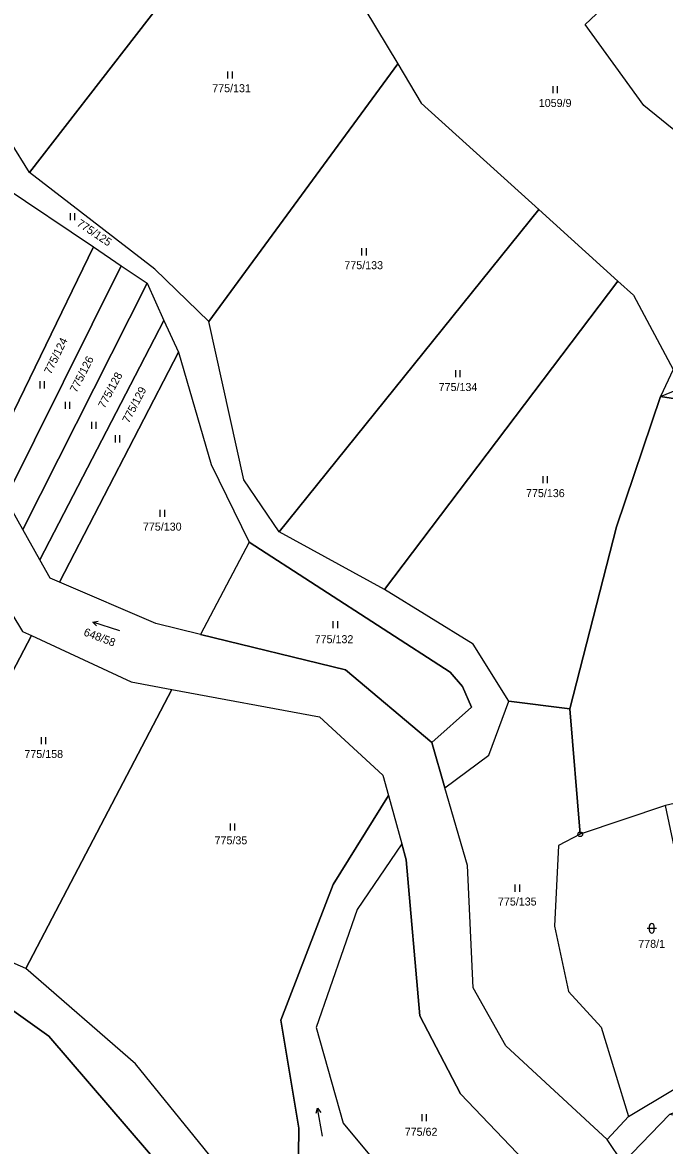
# Model space of a CAD drawing. Extents: x -654083 to -650132, y -1099819 to -1096699.
# Drawn here: x -653279.3 to -653142.9, y -1098231 to -1097992.4 of the extents above; entities that cross this region are included whole.
import ezdxf

# ---------------------------------------------------------------- set-up
doc = ezdxf.new("R2010")
doc.units = 0
for name, color, linetype in [('Geodetické body', 7, 'Continuous'), ('Obvody jako plochy', 7, 'Continuous'), ('Parcelní čísla', 7, 'Continuous'), ('Značky kultur', 7, 'Continuous')]:
    doc.layers.add(name, color=color, linetype=linetype)

msp = doc.modelspace()

# ---------------------------------------------------------------- linework, layer by layer
at = {"layer": 'Geodetické body'}
for radius in [0.5, 0.001]:
    msp.add_circle((-653160.81, -1098164.87), radius, dxfattribs=at)
at = {"layer": 'Obvody jako plochy'}
for points in [[(-653159.78, -1097992.82), (-653143.05, -1097977.01), (-653174.94, -1097944.83), (-653220.04, -1097975.33), (-653208.83, -1097985.73), (-653199.6, -1098001.2), (-653194.63, -1098009.53), (-653169.63, -1098032.13), (-653152.81, -1098047.34), (-653149.48, -1098050.35), (-653141.08, -1098066.12), (-653143.72, -1098071.82), (-653107.4, -1098056.94), (-653116.37, -1098047.99), (-653124.61, -1098033.31), (-653133.37, -1098021.26), (-653147.28, -1098010.02)], [(-653232.34, -1097965.52), (-653277.85, -1098024.22), (-653290.05, -1098004.68), (-653291.32, -1098003.86), (-653255.74, -1097953.38), (-653248.25, -1097960.84), (-653236.61, -1097962.12)], [(-653199.6, -1098001.2), (-653239.71, -1098055.94), (-653251.2, -1098044.79), (-653277.85, -1098024.22), (-653232.34, -1097965.52), (-653220.04, -1097975.33), (-653208.83, -1097985.73)], [(-653075.5, -1098032.29), (-653107.4, -1098056.94), (-653116.37, -1098047.99), (-653124.61, -1098033.31), (-653133.37, -1098021.26), (-653147.28, -1098010.02), (-653159.78, -1097992.82), (-653143.05, -1097977.01), (-653139.93, -1097974.11), (-653120.37, -1097998.7), (-653111.98, -1097991.16)], [(-653199.6, -1098001.2), (-653194.63, -1098009.53), (-653169.63, -1098032.13), (-653224.76, -1098100.64), (-653232.3, -1098089.58), (-653239.71, -1098055.94)], [(-653264.25, -1098040.07), (-653286.85, -1098086.54), (-653301, -1098061.42), (-653283.44, -1098027.14)], [(-653152.81, -1098047.34), (-653202.43, -1098112.89), (-653224.76, -1098100.64), (-653169.63, -1098032.13)], [(-653062.45, -1098049.88), (-653095.19, -1098080.64), (-653080.27, -1098096.44), (-653086.3, -1098093.39), (-653094.72, -1098096.79), (-653094.8, -1098106.24), (-653091.4, -1098111.38), (-653093.32, -1098113.17), (-653082.85, -1098128.85), (-653092.97, -1098135.64), (-653098.84, -1098139.62), (-653102.23, -1098135.55), (-653108.65, -1098140.04), (-653107.47, -1098141.62), (-653110.73, -1098144.07), (-653108.39, -1098146.98), (-653112.54, -1098150.18), (-653101.36, -1098101.34), (-653107.45, -1098091.76), (-653131.48, -1098073.76), (-653143.72, -1098071.82), (-653107.4, -1098056.94), (-653075.5, -1098032.29), (-653069, -1098038.01)], [(-653264.25, -1098040.07), (-653258.36, -1098044.1), (-653282.94, -1098093.51), (-653286.85, -1098086.54)], [(-653252.87, -1098047.8), (-653279.24, -1098100.09), (-653282.94, -1098093.51), (-653258.36, -1098044.1)], [(-653249.27, -1098055.67), (-653275.62, -1098106.54), (-653279.24, -1098100.09), (-653252.87, -1098047.8)], [(-653153.06, -1098099.55), (-653163, -1098138.19), (-653175.95, -1098136.58), (-653183.53, -1098124.46), (-653202.43, -1098112.89), (-653152.81, -1098047.34), (-653149.48, -1098050.35), (-653141.08, -1098066.12), (-653143.72, -1098071.82)], [(-653246.19, -1098062.4), (-653271.47, -1098111.27), (-653273.43, -1098110.43), (-653275.62, -1098106.54), (-653249.27, -1098055.67)], [(-653231.16, -1098102.79), (-653241.47, -1098122.39), (-653251.01, -1098120.05), (-653271.47, -1098111.27), (-653246.19, -1098062.4), (-653239.26, -1098086.27)], [(-653143.72, -1098071.82), (-653131.48, -1098073.76), (-653107.45, -1098091.76), (-653101.36, -1098101.34), (-653112.54, -1098150.18), (-653132.3, -1098156.38), (-653142.69, -1098158.75), (-653160.81, -1098164.87), (-653163, -1098138.19), (-653153.06, -1098099.55)], [(-653210.7, -1098129.94), (-653192.35, -1098145.37), (-653183.94, -1098137.86), (-653185.79, -1098133.47), (-653188.42, -1098130.41), (-653231.16, -1098102.79), (-653241.47, -1098122.39)], [(-653281.57, -1098118.02), (-653279.31, -1098121.79), (-653277.44, -1098122.65), (-653307.83, -1098180.61), (-653313.14, -1098178.29)], [(-653256.22, -1098132.47), (-653247.61, -1098134.08), (-653278.65, -1098193.38), (-653307.83, -1098180.61), (-653277.44, -1098122.65)], [(-653201.54, -1098156.66), (-653213.29, -1098175.51), (-653224.46, -1098204.35), (-653220.62, -1098227.34), (-653220.95, -1098256.03), (-653255.32, -1098213.68), (-653278.65, -1098193.38), (-653247.61, -1098134.08), (-653216.22, -1098139.94), (-653202.73, -1098152.28)], [(-653163.28, -1098198.26), (-653156.38, -1098205.89), (-653150.52, -1098224.84), (-653155.1, -1098229.74), (-653176.58, -1098209.82), (-653183.57, -1098197.47), (-653184.77, -1098171.52), (-653189.55, -1098155.03), (-653180.25, -1098148.05), (-653175.95, -1098136.58), (-653163, -1098138.19), (-653160.81, -1098164.87), (-653165.45, -1098167.24), (-653166.29, -1098184.39)], [(-653211.22, -1098226.27), (-653198.9, -1098241.01), (-653192.05, -1098259.39), (-653201.58, -1098268.37), (-653203.19, -1098270.41), (-653205.96, -1098270.01), (-653220.95, -1098256.03), (-653220.62, -1098227.34), (-653224.46, -1098204.35), (-653213.29, -1098175.51), (-653201.54, -1098156.66), (-653198.75, -1098166.88), (-653208.24, -1098180.85), (-653216.9, -1098205.95)], [(-653140.06, -1098171.16), (-653142.69, -1098158.75), (-653160.81, -1098164.87), (-653165.45, -1098167.24), (-653166.29, -1098184.39), (-653163.28, -1098198.26), (-653156.38, -1098205.89), (-653150.52, -1098224.84), (-653141.18, -1098219.21), (-653127.65, -1098213.56), (-653113.09, -1098212.74), (-653113.57, -1098209.43), (-653115.41, -1098203.29), (-653128.45, -1098206.67), (-653133.29, -1098186.91), (-653120.36, -1098183.92), (-653123.61, -1098174.68), (-653124.29, -1098173.63), (-653125.55, -1098167.69), (-653129.48, -1098168.54)], [(-653211.22, -1098226.27), (-653198.9, -1098241.01), (-653192.05, -1098259.39), (-653168.2, -1098238.96), (-653186.25, -1098220.02), (-653194.9, -1098203.46), (-653197.82, -1098170.31), (-653198.75, -1098166.88), (-653208.24, -1098180.85), (-653216.9, -1098205.95)], [(-653127.42, -1098218.94), (-653141.81, -1098224.4), (-653151.72, -1098234.65), (-653155.1, -1098229.74), (-653150.52, -1098224.84), (-653141.18, -1098219.21), (-653127.65, -1098213.56), (-653113.09, -1098212.74), (-653105.4, -1098235.64), (-653102.24, -1098235.17), (-653085.2, -1098247.42), (-653065.64, -1098241.83), (-653054.02, -1098216.68), (-653048.02, -1098219.45), (-653064.64, -1098245.21), (-653086.06, -1098253.64), (-653103.37, -1098243.32), (-653109.58, -1098237.03), (-653116.05, -1098224.73)], [(-653048.96, -1098245.31), (-653063.01, -1098264.63), (-653087.72, -1098268.11), (-653105.63, -1098249.24), (-653116.57, -1098235.54), (-653130.71, -1098226.18), (-653141.81, -1098224.4), (-653151.72, -1098234.65), (-653150.15, -1098236.92), (-653136.87, -1098239.39), (-653120.82, -1098247.61), (-653110.51, -1098257.89), (-653089.48, -1098275.9), (-653070.83, -1098275.94), (-653057.26, -1098272.93), (-653042.19, -1098261.25), (-653040.62, -1098245.28), (-653041.08, -1098237.12)]]:
    msp.add_lwpolyline(points, close=True, dxfattribs=at)
for points in [[(-653283.44, -1098027.14), (-653264.25, -1098040.07), (-653258.36, -1098044.1), (-653252.87, -1098047.8), (-653249.27, -1098055.67), (-653246.19, -1098062.4), (-653239.26, -1098086.27), (-653231.16, -1098102.79), (-653188.42, -1098130.41), (-653185.79, -1098133.47), (-653183.94, -1098137.86), (-653192.35, -1098145.37), (-653189.55, -1098155.03), (-653180.25, -1098148.05), (-653175.95, -1098136.58), (-653183.53, -1098124.46), (-653202.43, -1098112.89), (-653224.76, -1098100.64), (-653232.3, -1098089.58), (-653239.71, -1098055.94), (-653251.2, -1098044.79), (-653277.85, -1098024.22), (-653290.05, -1098004.68)], [(-653151.72, -1098234.65), (-653155.1, -1098229.74), (-653176.58, -1098209.82), (-653183.57, -1098197.47), (-653184.77, -1098171.52), (-653189.55, -1098155.03), (-653192.35, -1098145.37), (-653210.7, -1098129.94), (-653241.47, -1098122.39), (-653251.01, -1098120.05), (-653271.47, -1098111.27), (-653273.43, -1098110.43), (-653275.62, -1098106.54), (-653279.24, -1098100.09), (-653282.94, -1098093.51)], [(-653220.95, -1098256.03), (-653255.32, -1098213.68), (-653278.65, -1098193.38), (-653307.83, -1098180.61), (-653313.14, -1098178.29), (-653318.28, -1098177.23), (-653324.7, -1098175.91), (-653330.85, -1098174.66), (-653343.74, -1098171.99), (-653355.99, -1098171.56), (-653368.93, -1098171.02), (-653380.57, -1098166.58), (-653399.87, -1098159.66), (-653405.94, -1098157.48), (-653412.2, -1098155.23), (-653418.76, -1098152.53), (-653438.8, -1098143.39), (-653448.64, -1098138.64), (-653459.37, -1098133.66), (-653470.35, -1098127.79), (-653479.94, -1098122.66), (-653491.36, -1098116.55), (-653503.03, -1098110.31)], [(-653281.57, -1098118.02), (-653279.31, -1098121.79), (-653277.44, -1098122.65), (-653256.22, -1098132.47), (-653247.61, -1098134.08), (-653216.22, -1098139.94), (-653202.73, -1098152.28), (-653201.54, -1098156.66), (-653198.75, -1098166.88), (-653197.82, -1098170.31), (-653194.9, -1098203.46), (-653186.25, -1098220.02), (-653168.2, -1098238.96)], [(-653493.48, -1098120.72), (-653482.17, -1098127.04), (-653472.69, -1098132.34), (-653461.42, -1098138.22), (-653451, -1098142.87), (-653440.64, -1098147.5), (-653420.66, -1098156.42), (-653413.9, -1098158.8), (-653407.86, -1098160.93), (-653401.5, -1098163.17), (-653382.27, -1098169.95), (-653370.67, -1098173.73), (-653358.4, -1098174.67), (-653342.34, -1098175.9), (-653332.88, -1098178.02), (-653326.43, -1098179.47), (-653320.16, -1098180.87), (-653314.95, -1098182.04), (-653308.89, -1098183.4), (-653311.64, -1098188.12), (-653291.44, -1098195.15), (-653273.74, -1098207.76), (-653248.25, -1098237.42)], [(-653248.25, -1098237.42), (-653273.74, -1098207.76), (-653291.44, -1098195.15), (-653311.64, -1098188.12), (-653317.13, -1098186.57), (-653319.71, -1098185.85), (-653323.45, -1098187.25), (-653331.7, -1098190.34), (-653336.25, -1098192.05), (-653345, -1098208.95), (-653339.77, -1098228.47), (-653333.68, -1098254.4)]]:
    msp.add_lwpolyline(points, dxfattribs=at)
at = {"layer": 'Značky kultur'}
for p, q in [((-653235.75, -1098002.76), (-653235.75, -1098004.26)), ((-653234.72, -1098004.26), (-653234.72, -1098002.76)), ((-653166.64, -1098005.9), (-653166.64, -1098007.4)), ((-653165.61, -1098007.4), (-653165.61, -1098005.9)), ((-653269.21, -1098032.89), (-653269.21, -1098034.39)), ((-653268.19, -1098034.39), (-653268.19, -1098032.89)), ((-653207.28, -1098040.36), (-653207.28, -1098041.86)), ((-653206.26, -1098041.86), (-653206.26, -1098040.36)), ((-653187.32, -1098066.26), (-653187.32, -1098067.76)), ((-653186.3, -1098067.76), (-653186.3, -1098066.26)), ((-653275.67, -1098068.62), (-653275.67, -1098070.12)), ((-653274.65, -1098070.12), (-653274.65, -1098068.62)), ((-653270.29, -1098072.96), (-653270.29, -1098074.46)), ((-653269.27, -1098074.46), (-653269.27, -1098072.96)), ((-653264.67, -1098077.22), (-653264.67, -1098078.72)), ((-653263.65, -1098078.72), (-653263.65, -1098077.22)), ((-653259.65, -1098080.09), (-653259.65, -1098081.59)), ((-653258.62, -1098081.59), (-653258.62, -1098080.09)), ((-653168.76, -1098088.79), (-653168.76, -1098090.29)), ((-653167.73, -1098090.29), (-653167.73, -1098088.79)), ((-653250.15, -1098095.92), (-653250.15, -1098097.42)), ((-653249.12, -1098097.42), (-653249.12, -1098095.92)), ((-653258.68, -1098121.67), (-653264.38, -1098119.77)), ((-653213.36, -1098119.59), (-653213.36, -1098121.09)), ((-653212.33, -1098121.09), (-653212.33, -1098119.59)), ((-653275.37, -1098144.23), (-653275.37, -1098145.73)), ((-653274.34, -1098145.73), (-653274.34, -1098144.23)), ((-653235.2, -1098162.56), (-653235.2, -1098164.06)), ((-653234.18, -1098164.06), (-653234.18, -1098162.56)), ((-653174.69, -1098175.57), (-653174.69, -1098177.07)), ((-653173.67, -1098177.07), (-653173.67, -1098175.57)), ((-653146.6, -1098184.85), (-653144.6, -1098184.85)), ((-653146.1, -1098185.35), (-653146.1, -1098184.35)), ((-653145.1, -1098185.35), (-653145.1, -1098184.35)), ((-653215.59, -1098228.99), (-653216.63, -1098223.07)), ((-653194.49, -1098224.33), (-653194.49, -1098225.83)), ((-653193.46, -1098225.83), (-653193.46, -1098224.33))]:
    msp.add_line(p, q, dxfattribs=at)
for points in [[(-653263.59, -1098120.56), (-653264.38, -1098119.77), (-653263.27, -1098119.61)], [(-653216.95, -1098224.15), (-653216.63, -1098223.07), (-653215.96, -1098223.97)]]:
    msp.add_lwpolyline(points, dxfattribs=at)
for centre, start, end in [((-653145.6, -1098184.35), 0, 180), ((-653145.6, -1098185.35), 180, 0)]:
    msp.add_arc(centre, 0.5, start, end, dxfattribs=at)

# ---------------------------------------------------------------- texts
at = {"layer": 'Parcelní čísla'}
for s, p in [('775/131', (-653239.01, -1098007.19)), ('1059/9', (-653169.61, -1098010.33)), ('775/133', (-653210.93, -1098044.8)), ('775/134', (-653190.89, -1098070.69)), ('775/136', (-653172.32, -1098093.23)), ('775/130', (-653253.74, -1098100.35)), ('775/132', (-653217.24, -1098124.27)), ('775/158', (-653278.93, -1098148.66)), ('775/35', (-653238.51, -1098167)), ('775/135', (-653178.29, -1098180.01)), ('778/1', (-653148.47, -1098189)), ('775/62', (-653198.1, -1098228.94))]:
    msp.add_text(s, height=1.7, dxfattribs=at).set_placement(p)
for s, rotation, p in [('775/125', 326.268, (-653267.95, -1098035.45)), ('775/124', 63.864, (-653273.31, -1098067.26)), ('775/126', 63.117, (-653267.85, -1098071.16)), ('775/128', 61.974, (-653261.88, -1098074.52)), ('775/129', 62.487, (-653256.73, -1098077.65)), ('648/58', 339.408, (-653266.48, -1098122.57))]:
    msp.add_text(s, height=1.7, rotation=rotation, dxfattribs=at).set_placement(p)

doc.saveas('drawing.dxf')
